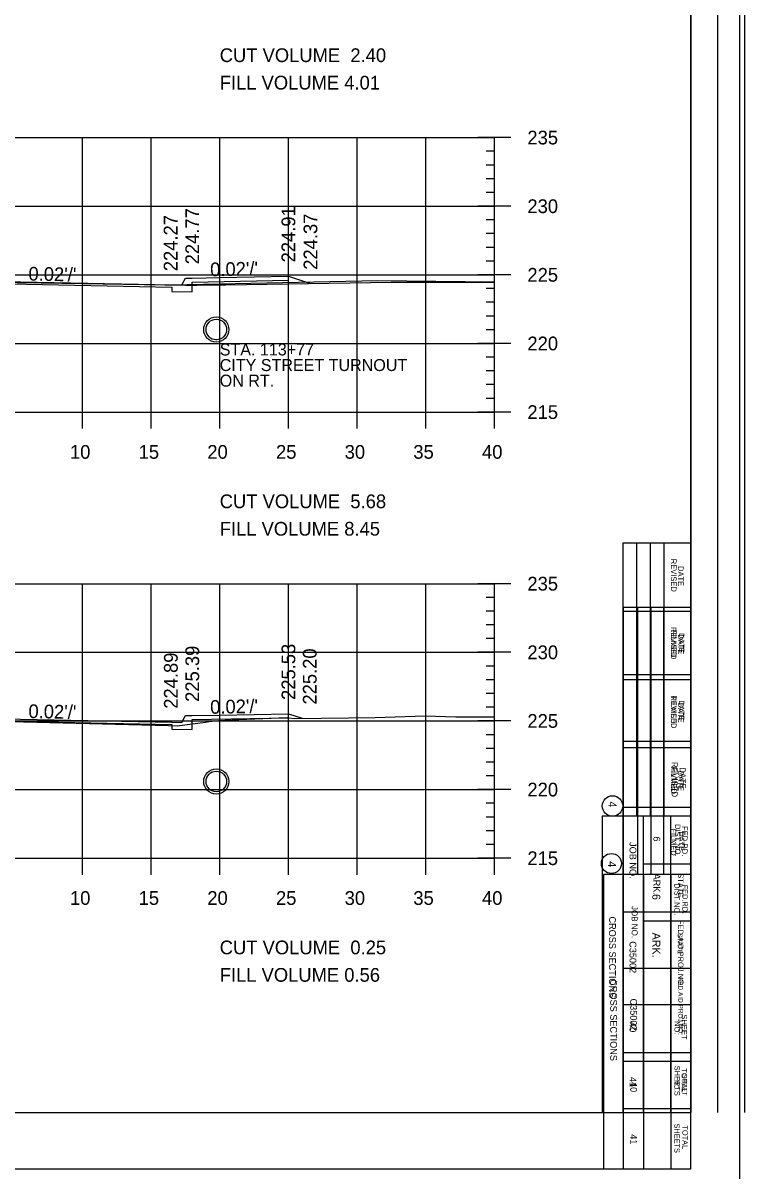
# Model space of a CAD drawing. Extents: x 1367903 to 1373764, y 376865 to 382130.
# Drawn here: x 1373420.9 to 1373526, y 377279.1 to 377447.5 of the extents above; entities that cross this region are included whole.
import ezdxf

# ---------------------------------------------------------------- set-up
doc = ezdxf.new("R2010")
doc.units = 0
for name, color, linetype in [('R_Axis', 7, 'Continuous'), ('R_Axis Annot', 7, 'Continuous'), ('R_Border', 7, 'Continuous'), ('R_Border Notes', 7, 'Continuous'), ('R_Border PE', 7, 'Continuous'), ('R_Draft', 7, 'Continuous'), ('R_Drive', 7, 'Continuous'), ('R_Exist Surface', 7, 'Continuous'), ('R_Fin Surface', 7, 'Continuous'), ('R_Fin Surface Annot', 7, 'Continuous'), ('R_Grid', 7, 'Continuous'), ('R_Water', 7, 'Continuous')]:
    doc.layers.add(name, color=color, linetype=linetype)

msp = doc.modelspace()

# ---------------------------------------------------------------- linework, layer by layer
for points in [[(1373373.57, 377410.37), (1373373.57, 377409.7), (1373373.57, 377409.7), (1373373.57, 377408.34), (1373376.57, 377408.4), (1373376.57, 377409.06), (1373409.57, 377409.72), (1373442.57, 377409.06), (1373442.57, 377408.4), (1373445.57, 377408.34), (1373445.57, 377409.78), (1373459.57, 377410.06), (1373459.57, 377410.65)], [(1373373.57, 377346.62), (1373373.57, 377345.95), (1373373.57, 377345.95), (1373373.57, 377344.59), (1373376.57, 377344.65), (1373376.57, 377345.32), (1373409.57, 377345.98), (1373442.57, 377345.32), (1373442.57, 377344.65), (1373445.57, 377344.59), (1373445.57, 377346.03), (1373459.57, 377346.31), (1373459.57, 377346.9)]]:
    msp.add_lwpolyline(points)
at = {"layer": 'R_Axis'}
for p, q in [((1373491.97, 377430.84), (1373487.17, 377430.84)), ((1373489.57, 377390.84), (1373489.57, 377430.84)), ((1373489.57, 377428.84), (1373488.37, 377428.84)), ((1373489.57, 377426.84), (1373488.37, 377426.84)), ((1373489.57, 377424.84), (1373488.37, 377424.84)), ((1373489.57, 377422.84), (1373488.37, 377422.84)), ((1373491.97, 377420.84), (1373487.17, 377420.84)), ((1373489.57, 377418.84), (1373488.37, 377418.84)), ((1373489.57, 377416.84), (1373488.37, 377416.84)), ((1373489.57, 377414.84), (1373488.37, 377414.84)), ((1373489.57, 377412.84), (1373488.37, 377412.84)), ((1373491.97, 377410.84), (1373487.17, 377410.84)), ((1373489.57, 377408.84), (1373488.37, 377408.84)), ((1373489.57, 377406.84), (1373488.37, 377406.84)), ((1373489.57, 377404.84), (1373488.37, 377404.84)), ((1373489.57, 377402.84), (1373488.37, 377402.84)), ((1373491.97, 377400.84), (1373487.17, 377400.84)), ((1373489.57, 377398.84), (1373488.37, 377398.84)), ((1373489.57, 377396.84), (1373488.37, 377396.84)), ((1373489.57, 377394.84), (1373488.37, 377394.84)), ((1373429.57, 377388.44), (1373429.57, 377393.24)), ((1373439.57, 377388.44), (1373439.57, 377393.24)), ((1373449.57, 377388.44), (1373449.57, 377393.24)), ((1373459.57, 377388.44), (1373459.57, 377393.24)), ((1373469.57, 377388.44), (1373469.57, 377393.24)), ((1373479.57, 377388.44), (1373479.57, 377393.24)), ((1373489.57, 377392.84), (1373488.37, 377392.84)), ((1373489.57, 377388.44), (1373489.57, 377393.24)), ((1373329.57, 377390.84), (1373489.57, 377390.84)), ((1373491.97, 377390.84), (1373487.17, 377390.84)), ((1373491.97, 377365.84), (1373487.17, 377365.84)), ((1373489.57, 377325.84), (1373489.57, 377365.84)), ((1373489.57, 377363.84), (1373488.37, 377363.84)), ((1373489.57, 377361.84), (1373488.37, 377361.84)), ((1373489.57, 377359.84), (1373488.37, 377359.84)), ((1373489.57, 377357.84), (1373488.37, 377357.84)), ((1373491.97, 377355.84), (1373487.17, 377355.84)), ((1373489.57, 377353.84), (1373488.37, 377353.84)), ((1373489.57, 377351.84), (1373488.37, 377351.84)), ((1373489.57, 377349.84), (1373488.37, 377349.84)), ((1373489.57, 377347.84), (1373488.37, 377347.84)), ((1373491.97, 377345.84), (1373487.17, 377345.84)), ((1373489.57, 377343.84), (1373488.37, 377343.84)), ((1373489.57, 377341.84), (1373488.37, 377341.84)), ((1373489.57, 377339.84), (1373488.37, 377339.84)), ((1373489.57, 377337.84), (1373488.37, 377337.84)), ((1373491.97, 377335.84), (1373487.17, 377335.84)), ((1373489.57, 377333.84), (1373488.37, 377333.84)), ((1373489.57, 377331.84), (1373488.37, 377331.84)), ((1373489.57, 377329.84), (1373488.37, 377329.84)), ((1373429.57, 377323.44), (1373429.57, 377328.24)), ((1373439.57, 377323.44), (1373439.57, 377328.24)), ((1373449.57, 377323.44), (1373449.57, 377328.24)), ((1373459.57, 377323.44), (1373459.57, 377328.24)), ((1373469.57, 377323.44), (1373469.57, 377328.24)), ((1373479.57, 377323.44), (1373479.57, 377328.24)), ((1373489.57, 377323.44), (1373489.57, 377328.24)), ((1373489.57, 377327.84), (1373488.37, 377327.84)), ((1373329.57, 377325.84), (1373489.57, 377325.84)), ((1373491.97, 377325.84), (1373487.17, 377325.84))]:
    msp.add_line(p, q, dxfattribs=at)
at = {"layer": 'R_Border'}
for p, q in [((1373525.23, 377620.35), (1373525.23, 377279.12)), ((1373518.19, 377280.59), (1373518.19, 377611.47)), ((1373518.19, 377446.03), (1373518.19, 377446.03)), ((1373508.38, 377280.59), (1373508.38, 377362.43)), ((1373508.38, 377362.43), (1373518.19, 377362.43)), ((1373508.38, 377362.43), (1373510.42, 377362.43)), ((1373510.42, 377362.43), (1373510.42, 377323.46)), ((1373512.36, 377362.43), (1373512.36, 377323.46)), ((1373514.21, 377362.43), (1373514.21, 377323.46)), ((1373508.38, 377352.62), (1373518, 377352.62)), ((1373508.38, 377342.9), (1373518, 377342.9)), ((1373508.38, 377333.27), (1373518, 377333.27)), ((1373518.19, 377323.46), (1373505.47, 377323.46)), ((1373505.47, 377323.46), (1373505.47, 377280.59)), ((1373511.3, 377280.59), (1373511.3, 377323.46)), ((1373515.28, 377280.59), (1373515.28, 377323.46)), ((1373518.19, 377316.65), (1373511.3, 377316.65)), ((1373518.19, 377309.75), (1373508.38, 377309.75)), ((1373518.19, 377296.24), (1373508.38, 377296.24)), ((1373518.19, 377289.33), (1373508.38, 377289.33)), ((1373313.87, 377280.59), (1373518.19, 377280.59))]:
    msp.add_line(p, q, dxfattribs=at)
msp.add_circle((1373506.6, 377325.07), 1.46, dxfattribs=at)
at = {"layer": 'R_Border PE'}
for p, q in [((1373522.12, 377288.8), (1373522.12, 377610.76)), ((1373526.04, 377288.8), (1373526.04, 377610.76)), ((1373518.19, 377603.25), (1373518.19, 377288.8)), ((1373508.25, 377371.74), (1373508.25, 377288.8)), ((1373518.19, 377371.74), (1373508.25, 377371.74)), ((1373510.24, 377371.74), (1373510.24, 377331.96)), ((1373512.23, 377371.74), (1373512.23, 377331.96)), ((1373514.22, 377371.74), (1373514.22, 377331.96)), ((1373518.19, 377361.8), (1373508.25, 377361.8)), ((1373518.19, 377351.85), (1373508.25, 377351.85)), ((1373518.19, 377341.91), (1373508.25, 377341.91)), ((1373505.26, 377331.96), (1373505.26, 377288.8)), ((1373518.19, 377331.96), (1373505.26, 377331.96)), ((1373511.23, 377331.96), (1373511.23, 377288.8)), ((1373515.21, 377331.96), (1373515.21, 377288.8)), ((1373511.29, 377325), (1373518.19, 377325)), ((1373508.38, 377318.04), (1373518.19, 377318.04)), ((1373508.38, 377304.51), (1373518.19, 377304.51)), ((1373508.38, 377297.55), (1373518.19, 377297.55)), ((1373313.87, 377288.8), (1373518.19, 377288.8)), ((1373515.3, 377288.8), (1373515.3, 377288.8))]:
    msp.add_line(p, q, dxfattribs=at)
msp.add_circle((1373506.76, 377333.45), 1.49, dxfattribs=at)
at = {"layer": 'R_Drive'}
for p, q in [((1373442.57, 377409.4), (1373472.56, 377410)), ((1373472.56, 377410), (1373489.57, 377409.8))]:
    msp.add_line(p, q, dxfattribs=at)
at = {"layer": 'R_Exist Surface'}
for points in [[(1373409.52, 377409.86), (1373423.59, 377409.67), (1373444.6, 377409.32), (1373444.89, 377409.31), (1373447.7, 377409.36), (1373450.48, 377409.39), (1373474.53, 377409.75), (1373477.31, 377409.77), (1373478.86, 377409.77), (1373482.37, 377409.77), (1373489.57, 377409.77)], [(1373409.5, 377346.02), (1373442.05, 377345.18), (1373443.49, 377345.14), (1373443.7, 377345.16), (1373447.48, 377345.68), (1373447.96, 377345.77), (1373449.41, 377345.92), (1373452.33, 377346.05), (1373459.41, 377346.34), (1373459.59, 377346.28), (1373460.49, 377346.21), (1373472.22, 377346.34), (1373479.47, 377346.59), (1373483.97, 377346.44), (1373489.57, 377346.43)]]:
    msp.add_lwpolyline(points, dxfattribs=at)
at = {"layer": 'R_Fin Surface'}
for points in [[(1373369.49, 377409.01), (1373373.57, 377410.37), (1373374.57, 377410.37), (1373375.07, 377409.37), (1373376.57, 377409.4), (1373398.57, 377409.84), (1373409.57, 377410.06), (1373420.57, 377409.84), (1373442.57, 377409.4), (1373444.07, 377409.37), (1373444.57, 377410.37), (1373445.57, 377410.37), (1373449.57, 377410.45), (1373459.57, 377410.65), (1373462.78, 377409.58)], [(1373369.59, 377345.29), (1373373.57, 377346.62), (1373374.57, 377346.62), (1373375.07, 377345.62), (1373376.57, 377345.65), (1373398.57, 377346.09), (1373409.57, 377346.31), (1373420.57, 377346.09), (1373442.57, 377345.65), (1373444.07, 377345.62), (1373444.57, 377346.62), (1373445.57, 377346.62), (1373449.57, 377346.7), (1373459.57, 377346.9), (1373461.59, 377346.23)]]:
    msp.add_lwpolyline(points, dxfattribs=at)
at = {"layer": 'R_Grid'}
for p, q in [((1373329.57, 377430.84), (1373489.57, 377430.84)), ((1373429.57, 377390.84), (1373429.57, 377430.84)), ((1373439.57, 377390.84), (1373439.57, 377430.84)), ((1373449.57, 377390.84), (1373449.57, 377430.84)), ((1373459.57, 377390.84), (1373459.57, 377430.84)), ((1373469.57, 377390.84), (1373469.57, 377430.84)), ((1373479.57, 377390.84), (1373479.57, 377430.84)), ((1373489.57, 377390.84), (1373489.57, 377430.84)), ((1373329.57, 377420.84), (1373489.57, 377420.84)), ((1373329.57, 377410.84), (1373489.57, 377410.84)), ((1373329.57, 377400.84), (1373489.57, 377400.84)), ((1373329.57, 377390.84), (1373489.57, 377390.84)), ((1373329.57, 377365.84), (1373489.57, 377365.84)), ((1373429.57, 377325.84), (1373429.57, 377365.84)), ((1373439.57, 377325.84), (1373439.57, 377365.84)), ((1373449.57, 377325.84), (1373449.57, 377365.84)), ((1373459.57, 377325.84), (1373459.57, 377365.84)), ((1373469.57, 377325.84), (1373469.57, 377365.84)), ((1373479.57, 377325.84), (1373479.57, 377365.84)), ((1373489.57, 377325.84), (1373489.57, 377365.84)), ((1373329.57, 377355.84), (1373489.57, 377355.84)), ((1373329.57, 377345.84), (1373489.57, 377345.84)), ((1373329.57, 377335.84), (1373489.57, 377335.84)), ((1373329.57, 377325.84), (1373489.57, 377325.84))]:
    msp.add_line(p, q, dxfattribs=at)
at = {"layer": 'R_Water'}
for p, q in [((1373449.07, 377404.73), (1373449.07, 377404.68)), ((1373449.07, 377404.39), (1373449.07, 377404.34)), ((1373449.07, 377401.39), (1373449.07, 377401.34)), ((1373449.07, 377401.06), (1373449.07, 377401.01)), ((1373449.07, 377338.87), (1373449.07, 377338.82)), ((1373449.07, 377338.54), (1373449.07, 377338.49)), ((1373449.07, 377335.54), (1373449.07, 377335.49)), ((1373449.07, 377335.21), (1373449.07, 377335.16))]:
    msp.add_line(p, q, dxfattribs=at)
for centre, radius in [((1373449.07, 377402.87), 1.83), ((1373449.07, 377402.87), 1.5), ((1373449.07, 377337.02), 1.83), ((1373449.07, 377337.02), 1.5)]:
    msp.add_circle(centre, radius, dxfattribs=at)

# ---------------------------------------------------------------- texts
at = {"layer": 'R_Axis Annot'}
for s, p in [('CUT VOLUME  2.40', (1373449.57, 377441.84)), ('FILL VOLUME 4.01', (1373449.57, 377437.84)), ('235', (1373494.37, 377429.84)), ('230', (1373494.37, 377419.84)), ('225', (1373494.37, 377409.84)), ('220', (1373494.37, 377399.84)), ('215', (1373494.37, 377389.84)), ('10', (1373427.76, 377384.04)), ('15', (1373437.76, 377384.04)), ('20', (1373447.76, 377384.04)), ('25', (1373457.76, 377384.04)), ('30', (1373467.76, 377384.04)), ('35', (1373477.76, 377384.04)), ('40', (1373487.76, 377384.04)), ('CUT VOLUME  5.68', (1373449.57, 377376.84)), ('FILL VOLUME 8.45', (1373449.57, 377372.84)), ('235', (1373494.37, 377364.84)), ('230', (1373494.37, 377354.84)), ('225', (1373494.37, 377344.84)), ('220', (1373494.37, 377334.84)), ('215', (1373494.37, 377324.84)), ('10', (1373427.76, 377319.04)), ('15', (1373437.76, 377319.04)), ('20', (1373447.76, 377319.04)), ('25', (1373457.76, 377319.04)), ('30', (1373467.76, 377319.04)), ('35', (1373477.76, 377319.04)), ('40', (1373487.76, 377319.04)), ('CUT VOLUME  0.25', (1373449.57, 377311.84)), ('FILL VOLUME 0.56', (1373449.57, 377307.84))]:
    msp.add_text(s, height=2, dxfattribs=at).set_placement(p)
at = {"layer": 'R_Border'}
for s, height, p in [('REVISED', 0.778, (1373515.28, 377359.51)), ('DATE', 0.778, (1373516.44, 377358.64)), ('FILMED', 0.778, (1373515.28, 377349.41)), ('DATE', 0.778, (1373516.44, 377348.82)), ('REVISED', 0.875, (1373515.38, 377339.88)), ('DATE', 0.875, (1373516.55, 377339.1)), ('FILMED', 0.778, (1373515.28, 377330.16)), ('DATE', 0.778, (1373516.44, 377329.77)), ('4', 1.17, (1373506.09, 377325.4)), ('DIST.NO.', 0.778, (1373515.77, 377322.19)), ('FED.RD.', 0.778, (1373516.94, 377321.99)), ('6', 1.17, (1373512.56, 377320.63)), ('JOB NO.', 0.875, (1373509.55, 377318.88)), ('ARK.', 1.166, (1373512.56, 377315)), ('STATE', 0.681, (1373516.25, 377314.9)), ('FED.AID PROJ.NO.', 0.6805, (1373516.35, 377308.49)), ('NO.', 0.681, (1373515.77, 377293.61)), ('SHEET', 0.681, (1373516.94, 377294.39)), ('SHEETS', 0.778, (1373515.77, 377287.2)), ('TOTAL', 0.778, (1373516.94, 377286.91))]:
    msp.add_text(s, height=height, rotation=270, dxfattribs=at).set_placement(p)
at = {"layer": 'R_Border Notes'}
for s, height, p in [('CROSS SECTIONS', 0.9945, (1373506.43, 377308.2)), ('C35002', 0.995, (1373509.34, 377305.39)), ('40', 0.995, (1373509.34, 377293.23)), ('41', 0.995, (1373509.34, 377285.62))]:
    msp.add_text(s, height=height, rotation=270, dxfattribs=at).set_placement(p)
at = {"layer": 'R_Border PE'}
for s, height, p in [('REVISED', 0.796, (1373515.29, 377369.47)), ('DATE', 0.796, (1373516.32, 377368.41)), ('FILMED', 0.796, (1373515.29, 377359.12)), ('DATE', 0.796, (1373516.32, 377358.47)), ('REVISED', 0.796, (1373515.29, 377349.57)), ('DATE', 0.796, (1373516.32, 377348.52)), ('FILMED', 0.796, (1373515.29, 377339.23)), ('DATE', 0.796, (1373516.32, 377338.58)), ('4', 1.19, (1373506.16, 377334.12)), ('DIST.NO.', 0.796, (1373515.86, 377330.83)), ('FED.RD.', 0.796, (1373516.9, 377330.52)), ('JOB NO.', 0.995, (1373509.24, 377328.19)), ('6', 0.995, (1373512.72, 377329.02)), ('ARK.', 0.995, (1373512.72, 377323.6)), ('STATE', 0.796, (1373516.3, 377323.66)), ('CROSS SECTIONS', 0.9945, (1373506.26, 377317.35)), ('FED.AID PROJ.NO.', 0.7956, (1373516.3, 377316.88)), ('C35002', 0.995, (1373509.24, 377313.75)), ('SHEET', 0.796, (1373516.82, 377303.09)), ('40', 0.995, (1373509.24, 377301.96)), ('NO.', 0.796, (1373515.79, 377302.11)), ('SHEETS', 0.796, (1373515.79, 377295.62)), ('TOTAL', 0.796, (1373516.82, 377295.23)), ('41', 0.995, (1373509.24, 377293.96))]:
    msp.add_text(s, height=height, rotation=270, dxfattribs=at).set_placement(p)
at = {"layer": 'R_Draft'}
for s, p in [('STA. 113+77', (1373449.57, 377399.09)), ('CITY STREET TURNOUT', (1373449.57, 377396.82)), ('ON RT.', (1373449.57, 377394.55))]:
    msp.add_text(s, height=1.75, dxfattribs=at).set_placement(p)
at = {"layer": 'R_Fin Surface Annot'}
for s, rotation, p in [('224.27', 90, (1373443.42, 377411.37)), ('224.77', 90, (1373446.57, 377412.37)), ('224.91', 90, (1373460.57, 377412.65)), ('224.37', 90, (1373463.78, 377411.58)), ("0.02'/'", 1.1458, (1373448.19, 377410.62)), ("0.02'/'", 358.8542, (1373421.7, 377410.01)), ('225.53', 90, (1373460.57, 377348.9)), ('224.89', 90, (1373443.45, 377347.62)), ('225.39', 90, (1373446.57, 377348.62)), ('225.20', 90, (1373463.68, 377348.23)), ("0.02'/'", 1.1458, (1373448.19, 377346.87)), ("0.02'/'", 358.8542, (1373421.7, 377346.27))]:
    msp.add_text(s, height=2, rotation=rotation, dxfattribs=at).set_placement(p)

doc.saveas('drawing.dxf')
